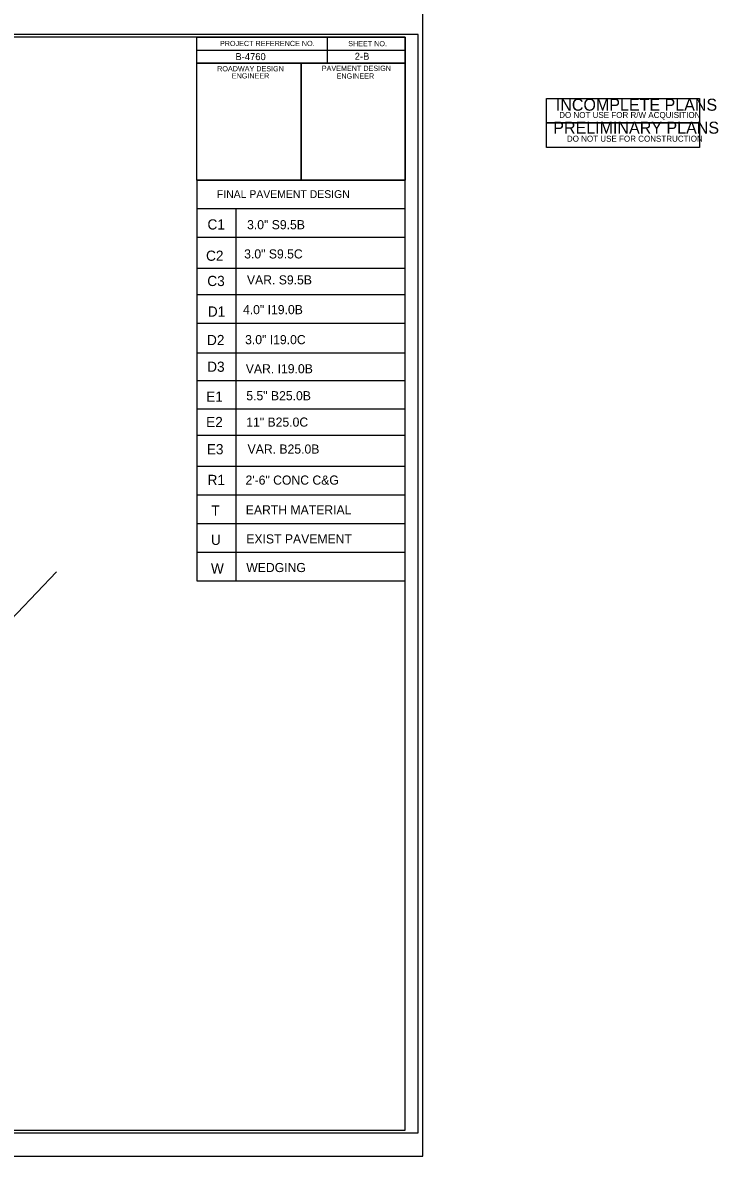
# Model space of a CAD drawing. Extents: x 981824 to 982276, y 44828 to 45204.
# Drawn here: x 982198.3 to 982251.8, y 44914 to 45001.1 of the extents above; entities that cross this region are included whole.
import ezdxf

# ---------------------------------------------------------------- set-up
doc = ezdxf.new("R2010")
doc.units = 0
for name, color, linetype in [('Old_Level_1', 7, 'Continuous'), ('Old_Level_11', 7, 'Continuous'), ('Old_Level_18', 7, 'Continuous'), ('Old_Level_19', 7, 'Continuous'), ('Old_Level_21', 7, 'Continuous'), ('Old_Level_40', 7, 'Continuous'), ('Old_Level_44', 7, 'Continuous'), ('Old_Level_50', 7, 'Continuous'), ('Old_Level_51', 7, 'Continuous'), ('Old_Level_52', 7, 'Continuous'), ('Sheet Sticker Incomplete CELL', 7, 'Continuous'), ('Sheet Sticker Preliminary CELL', 7, 'Continuous')]:
    doc.layers.add(name, color=color, linetype=linetype)

msp = doc.modelspace()

# ---------------------------------------------------------------- linework, layer by layer
at = {"layer": 'Old_Level_1'}
msp.add_line((982228.72, 45000.173), (982228.72, 45000.173), dxfattribs=at)
at = {"layer": 'Old_Level_11'}
msp.add_line((982187.764, 44945.108), (982200.941, 44958.877), dxfattribs=at)
at = {"layer": 'Old_Level_18'}
msp.add_lwpolyline([(982227.72, 44999.969), (982107.72, 44999.969), (982107.72, 44915.969), (982227.72, 44915.969)], close=True, dxfattribs=at)
at = {"layer": 'Old_Level_19'}
for p, q in [((982211.716, 44988.965), (982227.72, 44988.965)), ((982211.716, 44988.965), (982211.716, 44958.191)), ((982211.716, 44986.791), (982227.72, 44986.791)), ((982214.716, 44986.791), (982214.716, 44958.191)), ((982211.716, 44984.591), (982227.72, 44984.591)), ((982211.716, 44982.208), (982227.72, 44982.208)), ((982211.716, 44980.191), (982227.72, 44980.191)), ((982211.716, 44977.991), (982227.72, 44977.991)), ((982211.716, 44975.701), (982227.72, 44975.701)), ((982211.716, 44973.591), (982227.72, 44973.591)), ((982211.716, 44971.391), (982227.72, 44971.391)), ((982211.716, 44969.383), (982227.72, 44969.383)), ((982211.716, 44966.991), (982227.72, 44966.991)), ((982211.716, 44964.791), (982227.72, 44964.791)), ((982211.716, 44962.591), (982227.72, 44962.591)), ((982211.716, 44960.391), (982227.72, 44960.391)), ((982211.716, 44958.191), (982227.72, 44958.191))]:
    msp.add_line(p, q, dxfattribs=at)
at = {"layer": 'Old_Level_40'}
for p, q in [((982221.72, 44999.965), (982221.72, 44997.965)), ((982211.716, 44998.965), (982227.72, 44998.965)), ((982219.72, 44997.965), (982219.72, 44988.969))]:
    msp.add_line(p, q, dxfattribs=at)
for points in [[(982211.716, 44999.969), (982227.72, 44999.969), (982227.72, 44997.965), (982211.716, 44997.965)], [(982211.716, 44997.965), (982219.72, 44997.965), (982219.72, 44988.965), (982211.716, 44988.965)], [(982219.72, 44997.965), (982227.72, 44997.965), (982227.72, 44988.965), (982219.72, 44988.965)]]:
    msp.add_lwpolyline(points, close=True, dxfattribs=at)
at = {"layer": 'Old_Level_50'}
msp.add_lwpolyline([(982228.72, 45000.173), (982095.4, 45000.173), (982095.4, 44915.765), (982228.72, 44915.765)], close=True, dxfattribs=at)
at = {"layer": 'Old_Level_51'}
msp.add_lwpolyline([(982229.08, 45001.969), (982094.36, 45001.969), (982094.36, 44913.969), (982229.08, 44913.969)], close=True, dxfattribs=at)
at = {"layer": 'Old_Level_52'}
msp.add_line((982228.72, 45000.173), (982228.72, 45000.173), dxfattribs=at)
at = {"layer": 'Sheet Sticker Incomplete CELL'}
msp.add_lwpolyline([(982238.579, 44993.371), (982238.579, 44995.251), (982250.339, 44995.251), (982250.339, 44993.371)], close=True, dxfattribs=at)
at = {"layer": 'Sheet Sticker Preliminary CELL'}
msp.add_lwpolyline([(982238.579, 44991.491), (982238.579, 44993.371), (982250.339, 44993.371), (982250.339, 44991.491)], close=True, dxfattribs=at)

# ---------------------------------------------------------------- texts
at = {"layer": 'Old_Level_21'}
for s, height, p in [('FINAL PAVEMENT DESIGN', 0.6, (982213.253, 44987.599)), ('C1 ', 0.784, (982212.531, 44985.178)), ('3.0" S9.5B', 0.7, (982215.575, 44985.2)), ('C2', 0.784, (982212.421, 44982.774)), ('3.0" S9.5C', 0.7, (982215.351, 44982.955)), ('C3', 0.784, (982212.517, 44980.835)), ('VAR. S9.5B', 0.7, (982215.564, 44980.961)), ('D1 ', 0.784, (982212.556, 44978.485)), ('4.0" I19.0B', 0.7, (982215.26, 44978.674)), ('D2', 0.784, (982212.494, 44976.295)), ('3.0" I19.0C', 0.7, (982215.423, 44976.368)), ('D3', 0.784, (982212.508, 44974.246)), ('VAR. I19.0B', 0.7, (982215.476, 44974.133)), ('E1 ', 0.784, (982212.427, 44971.945)), ('5.5" B25.0B', 0.7, (982215.514, 44972.059)), ('E2', 0.784, (982212.424, 44969.996)), ('11" B25.0C', 0.7, (982215.511, 44970.033)), ('E3', 0.784, (982212.478, 44967.908)), ('VAR. B25.0B', 0.7, (982215.614, 44967.962)), ('R1 ', 0.784, (982212.538, 44965.547)), ('2\'-6" CONC C&G', 0.7, (982215.455, 44965.577)), ('T ', 0.784, (982212.826, 44963.199)), ('EARTH MATERIAL', 0.7, (982215.476, 44963.288)), ('U ', 0.784, (982212.799, 44960.945)), ('EXIST PAVEMENT', 0.7, (982215.514, 44961.059)), ('W ', 0.784, (982212.799, 44958.745)), ('WEDGING', 0.7, (982215.514, 44958.859))]:
    msp.add_text(s, height=height, dxfattribs=at).set_placement(p)
at = {"layer": 'Old_Level_44'}
for s, height, p in [('PROJECT REFERENCE NO.', 0.40001, (982213.492, 44999.273)), ('SHEET NO.', 0.4, (982223.344, 44999.265)), (' B-4760 ', 0.54, (982214.478, 44998.193)), ('2-B', 0.54, (982223.844, 44998.217)), ('PAVEMENT DESIGN', 0.40001, (982221.316, 44997.369)), ('ROADWAY DESIGN', 0.40001, (982213.276, 44997.333)), ('ENGINEER', 0.4, (982214.4, 44996.785)), ('ENGINEER', 0.4, (982222.452, 44996.773))]:
    msp.add_text(s, height=height, dxfattribs=at).set_placement(p)
at = {"layer": 'Sheet Sticker Incomplete CELL'}
for s, height, p in [('INCOMPLETE PLANS', 0.9216, (982239.295, 44994.307)), ('DO NOT USE FOR R/W ACQUISITION', 0.4608, (982239.555, 44993.751))]:
    msp.add_text(s, height=height, dxfattribs=at).set_placement(p)
at = {"layer": 'Sheet Sticker Preliminary CELL'}
for s, height, p in [('PRELIMINARY PLANS', 0.9216, (982239.099, 44992.543)), ('DO NOT USE FOR CONSTRUCTION', 0.4608, (982240.147, 44991.927))]:
    msp.add_text(s, height=height, dxfattribs=at).set_placement(p)

doc.saveas('drawing.dxf')
